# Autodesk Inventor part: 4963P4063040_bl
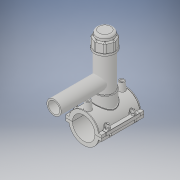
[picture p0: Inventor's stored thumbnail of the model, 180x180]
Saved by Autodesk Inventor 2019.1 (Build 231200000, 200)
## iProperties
Created: 2017-07
Part Number: 4963P4063040_bl
Material: Generic
Document SubType Name: Modeling
Designer: KIM
Density: 1 g/cm^3
Appearance: Default
Author: KIM
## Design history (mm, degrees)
derived "4963P4.ipt"
feature "Solid1::4963P4.ipt" dims "ScaleForDerivedMember" = 10
feature "Solid2::4963P4.ipt" dims "ScaleForDerivedMember" = 10
feature "Solid3::4963P4.ipt" dims "ScaleForDerivedMember" = 10
tag "TaggingFeature1"
body "Solid1"
body "Solid2"
body "Solid3"
other parameters: "d0" = 63 [user parameter], "d3" = 15.75 [user parameter], "d4" = 118 [user parameter], "d5" = 0 [user parameter], "d6" = 0.1 [user parameter], "d8" = 0 [user parameter], "d19" = 6 [user parameter], "d20" = 6 [user parameter], "d21" = 70.8 [user parameter], "d23" = 0 [user parameter], "d24" = 35.4 [user parameter], "d26" = 0 [user parameter], "d27" = 3 [user parameter], "d28" = 3 [user parameter], "d29" = 3 [user parameter], "d30" = 21 [user parameter], "d31" = 6 [user parameter], "d32" = 0 [user parameter], "d33" = 0 [user parameter], "d34" = 0.6 [user parameter], "d40" = 42.588 [user parameter], "d41" = 56.7 [user parameter], "d43" = 0 [user parameter], "d45" = 0 [user parameter], "d47" = 111.75 [user parameter], "d70" = 15 [user parameter], "d72" = 0 [user parameter], "d73" = 6 [user parameter], "d75" = 5 [user parameter], "d76" = 0 [user parameter], "d77" = 3.15 [user parameter], "d78" = 61.5 [user parameter], "d79" = 15 [user parameter], "d80" = 47.2 [user parameter], "d82" = 5 deg [user parameter], "d84" = 4 [user parameter], "d85" = 14 [user parameter], "d86" = 0 [user parameter], "d87" = 3 [user parameter], "d88" = 0 [user parameter], "d89" = 1 [user parameter], "d90" = 1 [user parameter], "d91" = 94.4 [user parameter], "d92" = 0 [user parameter], "d93" = 0.5 [user parameter], "d94" = 33.15789 [user parameter], "d96" = 83.538 [user parameter], "d97" = 2.36 [user parameter], "d98" = 0 [user parameter], "d102" = 0.63 [user parameter], "d120" = 140 deg [user parameter], "d121" = 24.228 [user parameter], "d122" = 20 deg [user parameter], "d123" = 163.8 [user parameter], "d124" = 49.14 [user parameter], "d126" = 0 [user parameter], "d143" = 64.89 [user parameter], "d145" = 14.53846 [user parameter], "d149" = 0.945 [user parameter], "d150" = 15.99231 [user parameter], "d153" = 118 [user parameter], "d154" = 0 [user parameter], "d156" = 40.95 [user parameter], "d157" = 160 deg [user parameter], "d159" = 3.78 [user parameter], "d161" = 0.945 [user parameter], "d162" = 70.8 [user parameter], "d163" = 0 [user parameter], "d164" = 31.5 [user parameter], "d167" = 6.3 [user parameter], "d168" = 39.95122 [user parameter], "d170" = 3.75 [user parameter], "d172" = 0 [user parameter], "d173" = 1 [user parameter], "d175" = 31.5 [user parameter], "d176" = 20 deg [user parameter], "d177" = 4.41 [user parameter], "d178" = 18.9 [user parameter], "d180" = 0 [user parameter], "d183" = 7.56 [user parameter], "d184" = 3.528 [user parameter], "d185" = 38.35 [user parameter], "d186" = 38.35 [user parameter], "d187" = 40.95 [user parameter], "d188" = 5.67 [user parameter], "d189" = 4.41 [user parameter], "d190" = 0 [user parameter], "d191" = 61.425 [user parameter], "d193" = 8 [user parameter], "d194" = 4.13 [user parameter], "d195" = 90 deg [user parameter], "d197" = 0 [user parameter], "d199" = 0 [user parameter], "d200" = 9.45 [user parameter], "d202" = 0 [user parameter], "d203" = 177 [user parameter], "d204" = 53.865 [user parameter], "d205" = 39.69 [user parameter], "d206" = 48.195 [user parameter], "d207" = 132.75 [user parameter], "d208" = 138.06 [user parameter], "d209" = 164.61 [user parameter], "d210" = 48.762 [user parameter], "d211" = 56.7 [user parameter], "d212" = 45.36 [user parameter], "d213" = 36 [user parameter], "d216" = 0 [user parameter], "d217" = 6.3 [user parameter], "d218" = 6.3 [user parameter], "d219" = 1.26 [user parameter], "d222" = 63 [user parameter], "d224" = 0 [user parameter], "d227" = 32 [user parameter], "d228" = 142 [user parameter], "d230" = 3.78 [user parameter], "d_" = 63 [user parameter], "L_" = 118 [user parameter], "d_t" = 6 [user parameter], "H_2" = 177 [user parameter], "H_" = 142 [user parameter]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
